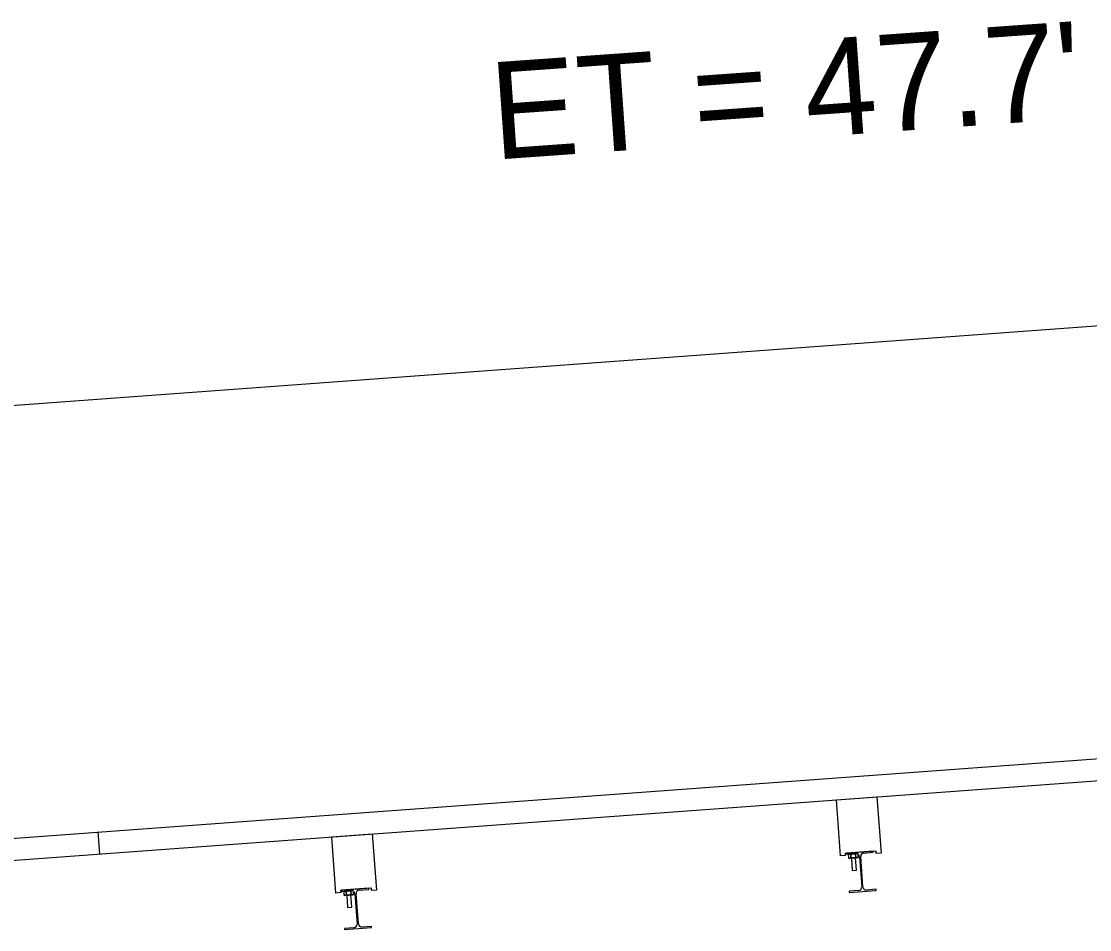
# Model space of a CAD drawing. Extents: x 16537443 to 16538473, y 7054586 to 7055469.
# Drawn here: x 16537491.19 to 16537504.39, y 7054589.03 to 7054600.24 of the extents above; entities that cross this region are included whole.
import ezdxf

# ---------------------------------------------------------------- set-up
doc = ezdxf.new("R2010")
doc.units = 0
doc.layers.add('Draft_DNC', color=7, linetype='Continuous')

msp = doc.modelspace()

# ---------------------------------------------------------------- linework, layer by layer
at = {"layer": 'Draft_DNC'}
for p, q in [((16537526.02, 7054598.061), (16537478.448, 7054594.568)), ((16537488.45, 7054589.962), (16537529.54, 7054592.98)), ((16537488.47, 7054589.692), (16537529.559, 7054592.71)), ((16537501.258, 7054590.631), (16537501.757, 7054590.668)), ((16537501.258, 7054590.631), (16537501.757, 7054590.668)), ((16537501.309, 7054589.937), (16537501.258, 7054590.631)), ((16537501.309, 7054589.937), (16537501.258, 7054590.631)), ((16537501.757, 7054590.668), (16537501.808, 7054589.973)), ((16537501.757, 7054590.668), (16537501.808, 7054589.973)), ((16537492.158, 7054589.963), (16537492.138, 7054590.233)), ((16537495.025, 7054590.173), (16537495.524, 7054590.21)), ((16537495.076, 7054589.479), (16537495.025, 7054590.173)), ((16537495.076, 7054589.479), (16537495.025, 7054590.173)), ((16537495.524, 7054590.21), (16537495.575, 7054589.516)), ((16537495.524, 7054590.21), (16537495.575, 7054589.516)), ((16537501.369, 7054589.972), (16537501.743, 7054590)), ((16537501.369, 7054589.972), (16537501.743, 7054590)), ((16537501.371, 7054589.941), (16537501.369, 7054589.972)), ((16537501.371, 7054589.941), (16537501.369, 7054589.972)), ((16537501.712, 7054589.998), (16537501.38, 7054589.973)), ((16537501.712, 7054589.998), (16537501.38, 7054589.973)), ((16537501.38, 7054589.973), (16537501.381, 7054589.958)), ((16537501.38, 7054589.973), (16537501.381, 7054589.958)), ((16537501.596, 7054589.973), (16537501.713, 7054589.982)), ((16537501.596, 7054589.973), (16537501.713, 7054589.982)), ((16537501.713, 7054589.982), (16537501.712, 7054589.998)), ((16537501.713, 7054589.982), (16537501.712, 7054589.998)), ((16537501.743, 7054590), (16537501.745, 7054589.969)), ((16537501.743, 7054590), (16537501.745, 7054589.969)), ((16537501.808, 7054589.973), (16537501.745, 7054589.969)), ((16537501.808, 7054589.973), (16537501.745, 7054589.969)), ((16537501.371, 7054589.941), (16537501.309, 7054589.937)), ((16537501.371, 7054589.941), (16537501.309, 7054589.937)), ((16537501.381, 7054589.958), (16537501.498, 7054589.966)), ((16537501.381, 7054589.958), (16537501.498, 7054589.966)), ((16537501.412, 7054589.96), (16537501.404, 7054589.954)), ((16537501.412, 7054589.96), (16537501.404, 7054589.954)), ((16537501.412, 7054589.96), (16537501.404, 7054589.954)), ((16537501.404, 7054589.954), (16537501.407, 7054589.913)), ((16537501.404, 7054589.954), (16537501.407, 7054589.913)), ((16537501.404, 7054589.954), (16537501.407, 7054589.913)), ((16537501.407, 7054589.913), (16537501.416, 7054589.908)), ((16537501.407, 7054589.913), (16537501.416, 7054589.908)), ((16537501.423, 7054589.909), (16537501.416, 7054589.908)), ((16537501.423, 7054589.909), (16537501.416, 7054589.908)), ((16537501.519, 7054589.916), (16537501.423, 7054589.909)), ((16537501.519, 7054589.916), (16537501.423, 7054589.909)), ((16537501.434, 7054589.956), (16537501.437, 7054589.915)), ((16537501.437, 7054589.915), (16537501.434, 7054589.956)), ((16537501.434, 7054589.956), (16537501.437, 7054589.915)), ((16537501.434, 7054589.956), (16537501.437, 7054589.915)), ((16537501.442, 7054589.91), (16537501.453, 7054589.759)), ((16537501.442, 7054589.91), (16537501.453, 7054589.759)), ((16537501.497, 7054589.919), (16537501.494, 7054589.961)), ((16537501.494, 7054589.961), (16537501.497, 7054589.919)), ((16537501.494, 7054589.961), (16537501.497, 7054589.919)), ((16537501.494, 7054589.961), (16537501.497, 7054589.919)), ((16537501.505, 7054589.763), (16537501.494, 7054589.914)), ((16537501.505, 7054589.763), (16537501.494, 7054589.914)), ((16537501.498, 7054589.966), (16537501.498, 7054589.966)), ((16537501.498, 7054589.966), (16537501.498, 7054589.966)), ((16537501.519, 7054589.916), (16537501.527, 7054589.921)), ((16537501.519, 7054589.916), (16537501.527, 7054589.921)), ((16537501.524, 7054589.959), (16537501.527, 7054589.921)), ((16537501.527, 7054589.921), (16537501.524, 7054589.959)), ((16537501.524, 7054589.959), (16537501.527, 7054589.921)), ((16537501.542, 7054589.928), (16537501.57, 7054589.554)), ((16537501.542, 7054589.928), (16537501.57, 7054589.554)), ((16537501.585, 7054589.555), (16537501.558, 7054589.929)), ((16537501.585, 7054589.555), (16537501.558, 7054589.929)), ((16537501.453, 7054589.759), (16537501.505, 7054589.763)), ((16537501.453, 7054589.759), (16537501.505, 7054589.763)), ((16537495.138, 7054589.484), (16537495.076, 7054589.479)), ((16537495.138, 7054589.484), (16537495.076, 7054589.479)), ((16537495.136, 7054589.515), (16537495.51, 7054589.542)), ((16537495.136, 7054589.515), (16537495.51, 7054589.542)), ((16537495.138, 7054589.484), (16537495.136, 7054589.515)), ((16537495.138, 7054589.484), (16537495.136, 7054589.515)), ((16537495.479, 7054589.54), (16537495.146, 7054589.515)), ((16537495.479, 7054589.54), (16537495.146, 7054589.515)), ((16537495.479, 7054589.54), (16537495.146, 7054589.515)), ((16537495.146, 7054589.515), (16537495.148, 7054589.5)), ((16537495.146, 7054589.515), (16537495.148, 7054589.5)), ((16537495.146, 7054589.515), (16537495.148, 7054589.5)), ((16537495.148, 7054589.5), (16537495.264, 7054589.508)), ((16537495.148, 7054589.5), (16537495.264, 7054589.508)), ((16537495.148, 7054589.5), (16537495.264, 7054589.508)), ((16537495.179, 7054589.502), (16537495.171, 7054589.496)), ((16537495.179, 7054589.502), (16537495.171, 7054589.496)), ((16537495.179, 7054589.502), (16537495.171, 7054589.496)), ((16537495.171, 7054589.496), (16537495.174, 7054589.455)), ((16537495.171, 7054589.496), (16537495.174, 7054589.455)), ((16537495.171, 7054589.496), (16537495.174, 7054589.455)), ((16537495.174, 7054589.455), (16537495.183, 7054589.45)), ((16537495.174, 7054589.455), (16537495.183, 7054589.45)), ((16537495.19, 7054589.451), (16537495.183, 7054589.45)), ((16537495.19, 7054589.451), (16537495.183, 7054589.45)), ((16537495.286, 7054589.458), (16537495.19, 7054589.451)), ((16537495.286, 7054589.458), (16537495.19, 7054589.451)), ((16537495.201, 7054589.499), (16537495.204, 7054589.457)), ((16537495.204, 7054589.457), (16537495.201, 7054589.499)), ((16537495.201, 7054589.499), (16537495.204, 7054589.457)), ((16537495.201, 7054589.499), (16537495.204, 7054589.457)), ((16537495.208, 7054589.452), (16537495.22, 7054589.302)), ((16537495.208, 7054589.452), (16537495.22, 7054589.302)), ((16537495.271, 7054589.305), (16537495.26, 7054589.456)), ((16537495.271, 7054589.305), (16537495.26, 7054589.456)), ((16537495.264, 7054589.461), (16537495.261, 7054589.503)), ((16537495.261, 7054589.503), (16537495.264, 7054589.461)), ((16537495.261, 7054589.503), (16537495.264, 7054589.461)), ((16537495.261, 7054589.503), (16537495.264, 7054589.461)), ((16537495.286, 7054589.458), (16537495.294, 7054589.464)), ((16537495.286, 7054589.458), (16537495.294, 7054589.464)), ((16537495.291, 7054589.501), (16537495.294, 7054589.464)), ((16537495.294, 7054589.464), (16537495.291, 7054589.501)), ((16537495.291, 7054589.501), (16537495.294, 7054589.464)), ((16537495.309, 7054589.47), (16537495.336, 7054589.096)), ((16537495.309, 7054589.47), (16537495.336, 7054589.096)), ((16537495.309, 7054589.47), (16537495.336, 7054589.096)), ((16537495.352, 7054589.097), (16537495.325, 7054589.471)), ((16537495.352, 7054589.097), (16537495.325, 7054589.471)), ((16537495.352, 7054589.097), (16537495.325, 7054589.471)), ((16537495.363, 7054589.516), (16537495.48, 7054589.524)), ((16537495.363, 7054589.516), (16537495.48, 7054589.524)), ((16537495.363, 7054589.516), (16537495.48, 7054589.524)), ((16537495.48, 7054589.524), (16537495.479, 7054589.54)), ((16537495.48, 7054589.524), (16537495.479, 7054589.54)), ((16537495.48, 7054589.524), (16537495.479, 7054589.54)), ((16537495.51, 7054589.542), (16537495.512, 7054589.511)), ((16537495.51, 7054589.542), (16537495.512, 7054589.511)), ((16537495.575, 7054589.516), (16537495.512, 7054589.511)), ((16537495.575, 7054589.516), (16537495.512, 7054589.511)), ((16537501.531, 7054589.509), (16537501.414, 7054589.501)), ((16537501.531, 7054589.509), (16537501.414, 7054589.501)), ((16537501.414, 7054589.501), (16537501.415, 7054589.485)), ((16537501.414, 7054589.501), (16537501.415, 7054589.485)), ((16537501.415, 7054589.485), (16537501.748, 7054589.509)), ((16537501.415, 7054589.485), (16537501.748, 7054589.509)), ((16537501.747, 7054589.525), (16537501.63, 7054589.516)), ((16537501.747, 7054589.525), (16537501.63, 7054589.516)), ((16537501.748, 7054589.509), (16537501.747, 7054589.525)), ((16537501.748, 7054589.509), (16537501.747, 7054589.525)), ((16537495.22, 7054589.302), (16537495.271, 7054589.305)), ((16537495.22, 7054589.302), (16537495.271, 7054589.305)), ((16537495.298, 7054589.051), (16537495.181, 7054589.043)), ((16537495.298, 7054589.051), (16537495.181, 7054589.043)), ((16537495.298, 7054589.051), (16537495.181, 7054589.043)), ((16537495.182, 7054589.027), (16537495.515, 7054589.052)), ((16537495.182, 7054589.027), (16537495.515, 7054589.052)), ((16537495.182, 7054589.027), (16537495.515, 7054589.052)), ((16537495.514, 7054589.067), (16537495.397, 7054589.059)), ((16537495.514, 7054589.067), (16537495.397, 7054589.059)), ((16537495.514, 7054589.067), (16537495.397, 7054589.059)), ((16537495.515, 7054589.052), (16537495.514, 7054589.067)), ((16537495.515, 7054589.052), (16537495.514, 7054589.067)), ((16537495.515, 7054589.052), (16537495.514, 7054589.067)), ((16537495.181, 7054589.043), (16537495.182, 7054589.027)), ((16537495.181, 7054589.043), (16537495.182, 7054589.027)), ((16537495.181, 7054589.043), (16537495.182, 7054589.027))]:
    msp.add_line(p, q, dxfattribs=at)
for points in [[(16537501.407, 7054589.913), (16537501.416, 7054589.908), (16537501.423, 7054589.909), (16537501.519, 7054589.916), (16537501.527, 7054589.921)], [(16537501.498, 7054589.966), (16537501.412, 7054589.96), (16537501.412, 7054589.96)], [(16537501.524, 7054589.959), (16537501.524, 7054589.959)], [(16537495.174, 7054589.455), (16537495.183, 7054589.45), (16537495.19, 7054589.451), (16537495.286, 7054589.458), (16537495.294, 7054589.464)], [(16537495.264, 7054589.508), (16537495.179, 7054589.502), (16537495.179, 7054589.502)], [(16537495.291, 7054589.501), (16537495.291, 7054589.501)]]:
    msp.add_lwpolyline(points, dxfattribs=at)
for points in [[(16537501.442, 7054589.91), (16537501.453, 7054589.759), (16537501.505, 7054589.763), (16537501.494, 7054589.914)], [(16537495.208, 7054589.452), (16537495.22, 7054589.302), (16537495.271, 7054589.305), (16537495.26, 7054589.456)]]:
    msp.add_lwpolyline(points, close=True, dxfattribs=at)
for centre, start, end in [((16537501.599, 7054589.932), 94.2076, 184.1966), ((16537501.599, 7054589.932), 94.2076, 184.1966), ((16537501.501, 7054589.925), 4.1936, 94.2028), ((16537501.501, 7054589.925), 55.0869, 94.2028), ((16537501.501, 7054589.925), 94.2017, 94.2028), ((16537501.501, 7054589.925), 4.1936, 94.2028), ((16537495.267, 7054589.467), 4.1936, 94.2028), ((16537495.267, 7054589.467), 4.1936, 94.2028), ((16537495.267, 7054589.467), 55.0869, 94.2028), ((16537495.267, 7054589.467), 4.1936, 94.2028), ((16537495.366, 7054589.474), 94.2076, 184.1966), ((16537495.366, 7054589.474), 94.2076, 184.1966), ((16537495.366, 7054589.474), 94.2076, 184.1966), ((16537501.528, 7054589.551), 274.2076, 4.1966), ((16537501.528, 7054589.551), 274.2076, 4.1966), ((16537501.627, 7054589.558), 184.1936, 274.2028), ((16537501.627, 7054589.558), 184.1936, 274.2028), ((16537495.295, 7054589.093), 274.2076, 4.1966), ((16537495.295, 7054589.093), 274.2076, 4.1966), ((16537495.295, 7054589.093), 274.2076, 4.1966), ((16537495.394, 7054589.1), 184.1936, 274.2028), ((16537495.394, 7054589.1), 184.1936, 274.2028), ((16537495.394, 7054589.1), 184.1936, 274.2028)]:
    msp.add_arc(centre, 0.0417, start, end, dxfattribs=at)
for points in [[(16537501.434, 7054589.956), (16537501.433, 7054589.957), (16537501.429, 7054589.959), (16537501.423, 7054589.961), (16537501.415, 7054589.96), (16537501.409, 7054589.957), (16537501.406, 7054589.955), (16537501.404, 7054589.954)], [(16537501.434, 7054589.956), (16537501.433, 7054589.957), (16537501.429, 7054589.959), (16537501.423, 7054589.961), (16537501.415, 7054589.96), (16537501.409, 7054589.957), (16537501.406, 7054589.955), (16537501.404, 7054589.954)], [(16537501.404, 7054589.954), (16537501.406, 7054589.955), (16537501.409, 7054589.957), (16537501.415, 7054589.96), (16537501.423, 7054589.961), (16537501.429, 7054589.959), (16537501.433, 7054589.957), (16537501.434, 7054589.956)], [(16537501.434, 7054589.956), (16537501.433, 7054589.957), (16537501.429, 7054589.959), (16537501.423, 7054589.961), (16537501.415, 7054589.96), (16537501.409, 7054589.957), (16537501.406, 7054589.955), (16537501.404, 7054589.954)], [(16537501.407, 7054589.913), (16537501.409, 7054589.912), (16537501.413, 7054589.91), (16537501.419, 7054589.908), (16537501.426, 7054589.909), (16537501.433, 7054589.912), (16537501.436, 7054589.914), (16537501.437, 7054589.915)], [(16537501.407, 7054589.913), (16537501.409, 7054589.912), (16537501.413, 7054589.91), (16537501.419, 7054589.908), (16537501.426, 7054589.909), (16537501.433, 7054589.912), (16537501.436, 7054589.914), (16537501.437, 7054589.915)], [(16537501.437, 7054589.915), (16537501.436, 7054589.914), (16537501.433, 7054589.912), (16537501.426, 7054589.909), (16537501.419, 7054589.908), (16537501.413, 7054589.91), (16537501.409, 7054589.912), (16537501.407, 7054589.913)], [(16537501.407, 7054589.913), (16537501.409, 7054589.912), (16537501.413, 7054589.91), (16537501.419, 7054589.908), (16537501.426, 7054589.909), (16537501.433, 7054589.912), (16537501.436, 7054589.914), (16537501.437, 7054589.915)], [(16537501.494, 7054589.961), (16537501.489, 7054589.962), (16537501.478, 7054589.964), (16537501.462, 7054589.964), (16537501.447, 7054589.961), (16537501.439, 7054589.958), (16537501.434, 7054589.956)], [(16537501.494, 7054589.961), (16537501.489, 7054589.962), (16537501.478, 7054589.964), (16537501.462, 7054589.964), (16537501.447, 7054589.961), (16537501.439, 7054589.958), (16537501.434, 7054589.956)], [(16537501.434, 7054589.956), (16537501.439, 7054589.958), (16537501.447, 7054589.961), (16537501.462, 7054589.964), (16537501.478, 7054589.964), (16537501.489, 7054589.962), (16537501.494, 7054589.961)], [(16537501.494, 7054589.961), (16537501.489, 7054589.962), (16537501.478, 7054589.964), (16537501.462, 7054589.964), (16537501.447, 7054589.961), (16537501.439, 7054589.958), (16537501.434, 7054589.956)], [(16537501.437, 7054589.915), (16537501.443, 7054589.914), (16537501.453, 7054589.912), (16537501.469, 7054589.912), (16537501.484, 7054589.914), (16537501.493, 7054589.918), (16537501.497, 7054589.919)], [(16537501.437, 7054589.915), (16537501.443, 7054589.914), (16537501.453, 7054589.912), (16537501.469, 7054589.912), (16537501.484, 7054589.914), (16537501.493, 7054589.918), (16537501.497, 7054589.919)], [(16537501.497, 7054589.919), (16537501.493, 7054589.918), (16537501.484, 7054589.914), (16537501.469, 7054589.912), (16537501.453, 7054589.912), (16537501.443, 7054589.914), (16537501.437, 7054589.915)], [(16537501.437, 7054589.915), (16537501.443, 7054589.914), (16537501.453, 7054589.912), (16537501.469, 7054589.912), (16537501.484, 7054589.914), (16537501.493, 7054589.918), (16537501.497, 7054589.919)], [(16537501.504, 7054589.966), (16537501.503, 7054589.965), (16537501.499, 7054589.964), (16537501.496, 7054589.962), (16537501.494, 7054589.961)], [(16537501.504, 7054589.966), (16537501.503, 7054589.965), (16537501.499, 7054589.964), (16537501.496, 7054589.962), (16537501.494, 7054589.961)], [(16537501.497, 7054589.919), (16537501.5, 7054589.918), (16537501.505, 7054589.915), (16537501.513, 7054589.915), (16537501.521, 7054589.917), (16537501.525, 7054589.92), (16537501.527, 7054589.921)], [(16537501.497, 7054589.919), (16537501.5, 7054589.918), (16537501.505, 7054589.915), (16537501.513, 7054589.915), (16537501.521, 7054589.917), (16537501.525, 7054589.92), (16537501.527, 7054589.921)], [(16537501.527, 7054589.921), (16537501.525, 7054589.92), (16537501.521, 7054589.917), (16537501.513, 7054589.915), (16537501.505, 7054589.915), (16537501.5, 7054589.918), (16537501.497, 7054589.919)], [(16537501.497, 7054589.919), (16537501.5, 7054589.918), (16537501.505, 7054589.915), (16537501.513, 7054589.915), (16537501.521, 7054589.917), (16537501.525, 7054589.92), (16537501.527, 7054589.921)], [(16537495.201, 7054589.499), (16537495.2, 7054589.499), (16537495.196, 7054589.501), (16537495.189, 7054589.503), (16537495.182, 7054589.502), (16537495.176, 7054589.5), (16537495.173, 7054589.498), (16537495.171, 7054589.496)], [(16537495.201, 7054589.499), (16537495.2, 7054589.499), (16537495.196, 7054589.501), (16537495.189, 7054589.503), (16537495.182, 7054589.502), (16537495.176, 7054589.5), (16537495.173, 7054589.498), (16537495.171, 7054589.496)], [(16537495.171, 7054589.496), (16537495.173, 7054589.498), (16537495.176, 7054589.5), (16537495.182, 7054589.502), (16537495.189, 7054589.503), (16537495.196, 7054589.501), (16537495.2, 7054589.499), (16537495.201, 7054589.499)], [(16537495.201, 7054589.499), (16537495.2, 7054589.499), (16537495.196, 7054589.501), (16537495.189, 7054589.503), (16537495.182, 7054589.502), (16537495.176, 7054589.5), (16537495.173, 7054589.498), (16537495.171, 7054589.496)], [(16537495.174, 7054589.455), (16537495.176, 7054589.454), (16537495.179, 7054589.452), (16537495.186, 7054589.451), (16537495.193, 7054589.451), (16537495.199, 7054589.454), (16537495.203, 7054589.456), (16537495.204, 7054589.457)], [(16537495.174, 7054589.455), (16537495.176, 7054589.454), (16537495.179, 7054589.452), (16537495.186, 7054589.451), (16537495.193, 7054589.451), (16537495.199, 7054589.454), (16537495.203, 7054589.456), (16537495.204, 7054589.457)], [(16537495.204, 7054589.457), (16537495.203, 7054589.456), (16537495.199, 7054589.454), (16537495.193, 7054589.451), (16537495.186, 7054589.451), (16537495.179, 7054589.452), (16537495.176, 7054589.454), (16537495.174, 7054589.455)], [(16537495.174, 7054589.455), (16537495.176, 7054589.454), (16537495.179, 7054589.452), (16537495.186, 7054589.451), (16537495.193, 7054589.451), (16537495.199, 7054589.454), (16537495.203, 7054589.456), (16537495.204, 7054589.457)], [(16537495.261, 7054589.503), (16537495.256, 7054589.504), (16537495.245, 7054589.506), (16537495.229, 7054589.506), (16537495.214, 7054589.503), (16537495.205, 7054589.5), (16537495.201, 7054589.499)], [(16537495.261, 7054589.503), (16537495.256, 7054589.504), (16537495.245, 7054589.506), (16537495.229, 7054589.506), (16537495.214, 7054589.503), (16537495.205, 7054589.5), (16537495.201, 7054589.499)], [(16537495.201, 7054589.499), (16537495.205, 7054589.5), (16537495.214, 7054589.503), (16537495.229, 7054589.506), (16537495.245, 7054589.506), (16537495.256, 7054589.504), (16537495.261, 7054589.503)], [(16537495.261, 7054589.503), (16537495.256, 7054589.504), (16537495.245, 7054589.506), (16537495.229, 7054589.506), (16537495.214, 7054589.503), (16537495.205, 7054589.5), (16537495.201, 7054589.499)], [(16537495.204, 7054589.457), (16537495.209, 7054589.456), (16537495.22, 7054589.454), (16537495.236, 7054589.454), (16537495.251, 7054589.457), (16537495.26, 7054589.46), (16537495.264, 7054589.461)], [(16537495.204, 7054589.457), (16537495.209, 7054589.456), (16537495.22, 7054589.454), (16537495.236, 7054589.454), (16537495.251, 7054589.457), (16537495.26, 7054589.46), (16537495.264, 7054589.461)], [(16537495.264, 7054589.461), (16537495.26, 7054589.46), (16537495.251, 7054589.457), (16537495.236, 7054589.454), (16537495.22, 7054589.454), (16537495.209, 7054589.456), (16537495.204, 7054589.457)], [(16537495.204, 7054589.457), (16537495.209, 7054589.456), (16537495.22, 7054589.454), (16537495.236, 7054589.454), (16537495.251, 7054589.457), (16537495.26, 7054589.46), (16537495.264, 7054589.461)], [(16537495.271, 7054589.508), (16537495.27, 7054589.508), (16537495.266, 7054589.507), (16537495.263, 7054589.505), (16537495.261, 7054589.503)], [(16537495.271, 7054589.508), (16537495.27, 7054589.508), (16537495.266, 7054589.507), (16537495.263, 7054589.505), (16537495.261, 7054589.503)], [(16537495.264, 7054589.461), (16537495.267, 7054589.46), (16537495.272, 7054589.458), (16537495.28, 7054589.457), (16537495.288, 7054589.459), (16537495.292, 7054589.462), (16537495.294, 7054589.464)], [(16537495.264, 7054589.461), (16537495.267, 7054589.46), (16537495.272, 7054589.458), (16537495.28, 7054589.457), (16537495.288, 7054589.459), (16537495.292, 7054589.462), (16537495.294, 7054589.464)], [(16537495.294, 7054589.464), (16537495.292, 7054589.462), (16537495.288, 7054589.459), (16537495.28, 7054589.457), (16537495.272, 7054589.458), (16537495.267, 7054589.46), (16537495.264, 7054589.461)], [(16537495.264, 7054589.461), (16537495.267, 7054589.46), (16537495.272, 7054589.458), (16537495.28, 7054589.457), (16537495.288, 7054589.459), (16537495.292, 7054589.462), (16537495.294, 7054589.464)]]:
    msp.add_open_spline(points, degree=3, dxfattribs=at)

# ---------------------------------------------------------------- texts
msp.add_text("ET = 47.7'", height=1.2, rotation=4.055, dxfattribs=at).set_placement((16537497.031, 7054598.534))

doc.saveas('drawing.dxf')
